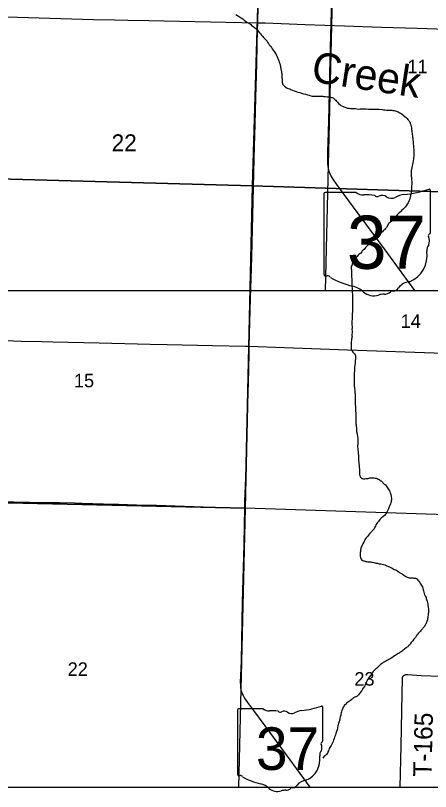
# Model space of a CAD drawing. Extents: x 0 to 68, y 0 to 52.9.
# Drawn here: x 47.275 to 48.632, y 31.129 to 33.667 of the extents above; entities that cross this region are included whole.
import ezdxf

# ---------------------------------------------------------------- set-up
doc = ezdxf.new("R2010")
doc.units = 0
for name, color, linetype in [('Default', 7, 'Continuous'), ('GM_X_Minor_River', 7, 'Continuous'), ('GM_X_Minor_River_Text', 7, 'Continuous'), ('GM_X_State_Route', 7, 'Continuous'), ('GM_X_State_Shield', 7, 'Continuous'), ('GM_X_Township_Road', 7, 'Continuous'), ('GM_X_Township_Road_Text', 7, 'Continuous')]:
    doc.layers.add(name, color=color, linetype=linetype)

msp = doc.modelspace()

# ---------------------------------------------------------------- linework, layer by layer
at = {"layer": 'Default'}
for p, q in [((41.1051, 32.7683), (50.3451, 32.7683)), ((42.2581, 31.1431), (49.6501, 31.1431))]:
    msp.add_line(p, q, dxfattribs=at)
for points in [[(47.0084, 34.1977), (48.0815, 34.1703), (48.0507, 33.11), (46.9804, 33.1394)], [(48.0815, 34.1703), (49.1337, 34.1352), (49.1093, 33.076), (48.0507, 33.11)], [(46.9804, 33.1394), (48.0507, 33.11), (48.0259, 32.0553), (46.9572, 32.0794)], [(48.0507, 33.11), (49.1093, 33.076), (49.0797, 32.0205), (48.0259, 32.0553)]]:
    msp.add_lwpolyline(points, close=True, dxfattribs=at)
for points in [[(46.955, 32.7683), (46.979, 33.9387), (48.3149, 33.9086), (48.2876, 32.7683)], [(46.938, 31.1431), (46.9572, 32.0794), (48.0259, 32.0553), (48.0041, 31.1431)]]:
    msp.add_lwpolyline(points, dxfattribs=at)
at = {"layer": 'GM_X_Minor_River'}
for points in [[(47.9962, 33.6707), (48.0006, 33.6671), (48.0078, 33.6631), (48.013, 33.6598), (48.0182, 33.6562), (48.023, 33.6526), (48.0278, 33.649), (48.0318, 33.6461), (48.0358, 33.6441), (48.0382, 33.6425), (48.0402, 33.6409), (48.0422, 33.6393), (48.0446, 33.6377), (48.0478, 33.634), (48.0527, 33.6316), (48.0555, 33.6292), (48.0583, 33.6272), (48.0611, 33.6248), (48.0639, 33.6224), (48.0663, 33.6191), (48.0695, 33.6147), (48.0731, 33.6111), (48.0763, 33.6075), (48.0795, 33.6034), (48.0831, 33.5994), (48.0875, 33.5942), (48.0911, 33.5906), (48.0943, 33.5877), (48.0963, 33.5857), (48.0979, 33.5833), (48.0995, 33.5801), (48.1023, 33.5761), (48.1051, 33.5713), (48.1087, 33.5668), (48.1119, 33.5624), (48.1147, 33.5584), (48.1179, 33.5536), (48.1211, 33.5499), (48.1231, 33.5463), (48.1255, 33.5427), (48.1279, 33.5395), (48.1291, 33.5367), (48.1307, 33.5326), (48.1363, 33.5194), (48.1375, 33.5154), (48.1391, 33.5109), (48.1407, 33.5053), (48.1419, 33.5017), (48.1423, 33.4989), (48.1431, 33.4957), (48.1434, 33.4921)], [(48.1434, 33.4921), (48.1442, 33.4897), (48.1442, 33.4873), (48.1446, 33.4844), (48.145, 33.4812), (48.1458, 33.4776), (48.1462, 33.4744), (48.1466, 33.4716), (48.1466, 33.4676), (48.1466, 33.4644), (48.147, 33.4612), (48.147, 33.4567), (48.147, 33.4531), (48.147, 33.4507), (48.1474, 33.4483), (48.1482, 33.4447), (48.1486, 33.4427), (48.1502, 33.4407), (48.1522, 33.4387), (48.1546, 33.4359), (48.159, 33.4326), (48.1634, 33.4302), (48.1678, 33.4286), (48.1718, 33.4274), (48.1758, 33.4257), (48.1806, 33.4233), (48.187, 33.4213), (48.1931, 33.4189), (48.1987, 33.4168), (48.2047, 33.4152), (48.2107, 33.4132), (48.2175, 33.4116), (48.2239, 33.4099), (48.23, 33.4083), (48.236, 33.4067), (48.2408, 33.4051), (48.2456, 33.4039), (48.2516, 33.4034), (48.2653, 33.4038), (48.2697, 33.4038), (48.2733, 33.4038), (48.2757, 33.4038), (48.2781, 33.4037), (48.2805, 33.4033), (48.2829, 33.4029), (48.2861, 33.4025), (48.2893, 33.4021), (48.2942, 33.4017), (48.2974, 33.4017), (48.301, 33.4013), (48.303, 33.4009), (48.3054, 33.4004), (48.3082, 33.3996), (48.3106, 33.3992), (48.3138, 33.398), (48.3166, 33.396), (48.3198, 33.3932), (48.3226, 33.3904), (48.3254, 33.3871), (48.3282, 33.3835), (48.3318, 33.3795), (48.3354, 33.3759), (48.3394, 33.373), (48.3443, 33.371), (48.3495, 33.3686), (48.3559, 33.3666), (48.3615, 33.3649), (48.3659, 33.3641), (48.3707, 33.3637), (48.3743, 33.3637), (48.378, 33.3637), (48.382, 33.3637), (48.3868, 33.3629), (48.3916, 33.362), (48.3968, 33.3616), (48.402, 33.362), (48.4061, 33.3624), (48.4101, 33.3624), (48.4141, 33.3624), (48.4217, 33.3619), (48.4297, 33.3615), (48.4374, 33.3611), (48.4454, 33.3611), (48.453, 33.3614), (48.4586, 33.361), (48.4634, 33.3606), (48.4747, 33.3602), (48.4787, 33.3594), (48.4835, 33.3585), (48.4891, 33.3581), (48.4931, 33.3581), (48.4972, 33.3581), (48.5012, 33.3581), (48.5056, 33.3577), (48.5096, 33.3572), (48.5136, 33.3564), (48.5172, 33.3556), (48.5208, 33.3548), (48.5236, 33.3536), (48.5268, 33.3524), (48.5317, 33.3495)], [(48.5317, 33.3495), (48.5365, 33.3467), (48.5409, 33.3439), (48.5445, 33.3407), (48.5489, 33.337), (48.5525, 33.3342), (48.5561, 33.331), (48.5589, 33.3274), (48.5617, 33.3238), (48.5641, 33.3201), (48.5657, 33.3173), (48.5665, 33.3137), (48.5677, 33.3101), (48.5689, 33.3049), (48.5701, 33.3001), (48.5709, 33.2976), (48.5709, 33.2948), (48.5713, 33.2912), (48.5716, 33.2864), (48.572, 33.282), (48.5728, 33.278), (48.5732, 33.2744), (48.5736, 33.2704), (48.5744, 33.2647), (48.5748, 33.2595), (48.5756, 33.2551), (48.576, 33.2511), (48.576, 33.2467), (48.5764, 33.2423), (48.5764, 33.239), (48.5771, 33.235), (48.5775, 33.2298), (48.5775, 33.2258), (48.5779, 33.2218), (48.5779, 33.2162), (48.5779, 33.2113), (48.5771, 33.1985), (48.5762, 33.1921), (48.575, 33.1853), (48.5738, 33.1801), (48.5726, 33.1756), (48.5714, 33.1704), (48.5702, 33.1648), (48.5693, 33.1596), (48.5689, 33.1536), (48.5689, 33.148), (48.5693, 33.1423), (48.5701, 33.1383), (48.5705, 33.1339), (48.5709, 33.1291), (48.5713, 33.1247), (48.5713, 33.1203), (48.5713, 33.1151), (48.5708, 33.1098), (48.5708, 33.1054), (48.5704, 33.1006), (48.5704, 33.0958), (48.57, 33.0918), (48.5696, 33.0886), (48.5688, 33.0842), (48.5676, 33.0793), (48.5667, 33.0757), (48.5659, 33.0733), (48.5647, 33.0697), (48.5635, 33.0649), (48.5623, 33.0621), (48.5611, 33.0601), (48.5591, 33.0549), (48.5575, 33.0509), (48.5546, 33.0477), (48.5534, 33.0449), (48.551, 33.0421), (48.5486, 33.0397), (48.5466, 33.0373), (48.5442, 33.0353), (48.5418, 33.0325), (48.5381, 33.0293), (48.5349, 33.0253), (48.5305, 33.0217), (48.5269, 33.0185), (48.5237, 33.0149), (48.5204, 33.0113), (48.5172, 33.0077), (48.5144, 33.0045), (48.512, 33.0021), (48.5039, 32.9941), (48.5015, 32.9921), (48.4987, 32.9897), (48.4967, 32.9885), (48.4951, 32.9865), (48.4902, 32.9765), (48.4886, 32.9741), (48.4866, 32.9717), (48.4842, 32.9693), (48.4818, 32.9669), (48.4798, 32.9649), (48.4778, 32.9629), (48.4754, 32.9597), (48.4713, 32.9573), (48.4685, 32.9549), (48.4653, 32.9529)], [(48.4653, 32.9529), (48.4629, 32.9509), (48.4601, 32.9481), (48.4569, 32.9449), (48.4536, 32.9425), (48.45, 32.9397), (48.4468, 32.9369), (48.444, 32.9345), (48.4412, 32.9321), (48.438, 32.9285), (48.4351, 32.9253), (48.4319, 32.9217), (48.4283, 32.9173), (48.4247, 32.9133), (48.4215, 32.9097), (48.4182, 32.9057), (48.415, 32.9025), (48.4122, 32.8997), (48.4094, 32.8973), (48.4074, 32.8945), (48.4046, 32.8901), (48.3997, 32.8869), (48.3961, 32.8833), (48.3925, 32.8793), (48.3893, 32.8761), (48.3865, 32.8733), (48.3844, 32.8705), (48.382, 32.8673), (48.3804, 32.864), (48.3788, 32.8612), (48.3772, 32.8576), (48.376, 32.8544), (48.3748, 32.8492), (48.3735, 32.846), (48.3735, 32.8428), (48.3735, 32.8392), (48.3739, 32.836), (48.3739, 32.8328), (48.3739, 32.83), (48.3739, 32.8259), (48.3743, 32.8123), (48.3747, 32.8059), (48.375, 32.8007), (48.375, 32.7946), (48.375, 32.7886), (48.3754, 32.7822), (48.3758, 32.775), (48.3762, 32.7681), (48.3766, 32.7613), (48.3769, 32.7553), (48.3773, 32.7493), (48.3777, 32.7441), (48.3777, 32.74), (48.3777, 32.7332), (48.3773, 32.7268), (48.3773, 32.7216), (48.3772, 32.7152), (48.3772, 32.7063), (48.3772, 32.6983), (48.3768, 32.6923), (48.3768, 32.6883), (48.3768, 32.6835), (48.3764, 32.6779), (48.3759, 32.6734), (48.3755, 32.6686), (48.3755, 32.6638), (48.3755, 32.6586), (48.3755, 32.6542), (48.3759, 32.6506), (48.3759, 32.6461), (48.3755, 32.6405), (48.3759, 32.6357), (48.3758, 32.6305), (48.3754, 32.6241), (48.3754, 32.6197), (48.3758, 32.6173), (48.3754, 32.614), (48.375, 32.612), (48.3746, 32.6088), (48.3742, 32.6064), (48.3742, 32.604), (48.3734, 32.5996), (48.373, 32.5964), (48.3725, 32.5936), (48.3725, 32.59), (48.3725, 32.586), (48.3725, 32.5832), (48.3725, 32.5811), (48.3725, 32.5783), (48.3733, 32.5763), (48.3757, 32.5719), (48.3789, 32.5659), (48.3837, 32.561), (48.3861, 32.5578), (48.3873, 32.5558), (48.3877, 32.5534), (48.3877, 32.5502), (48.3877, 32.547), (48.3873, 32.5426), (48.3865, 32.539), (48.3861, 32.5346)], [(48.3861, 32.5346), (48.386, 32.5297), (48.3852, 32.5233), (48.3844, 32.5157), (48.384, 32.5101), (48.3836, 32.5041), (48.3832, 32.498), (48.3827, 32.4912), (48.3827, 32.486), (48.3827, 32.4804), (48.3827, 32.474), (48.3827, 32.4655), (48.3827, 32.4607), (48.3831, 32.4563), (48.3834, 32.4479), (48.3846, 32.4394), (48.3854, 32.4334), (48.3862, 32.4302), (48.3866, 32.427), (48.3866, 32.423), (48.3862, 32.4105), (48.3862, 32.4053), (48.3861, 32.4013), (48.3865, 32.3989), (48.3865, 32.3969), (48.3865, 32.3937), (48.3869, 32.3909), (48.3873, 32.3885), (48.3877, 32.3857), (48.3877, 32.3816), (48.3877, 32.3764), (48.3877, 32.3724), (48.3881, 32.37), (48.3881, 32.3672), (48.3881, 32.3632), (48.3885, 32.3592), (48.388, 32.3564), (48.388, 32.3528), (48.388, 32.3483), (48.388, 32.3447), (48.388, 32.3395), (48.3884, 32.3355), (48.3884, 32.3319), (48.3888, 32.3283), (48.3896, 32.3243), (48.39, 32.319), (48.3903, 32.313), (48.3907, 32.3062), (48.3923, 32.2986), (48.3939, 32.2905), (48.3947, 32.2841), (48.3947, 32.2785), (48.3943, 32.2717), (48.3943, 32.2665), (48.3942, 32.2612), (48.395, 32.2456), (48.3954, 32.2404), (48.3962, 32.2347), (48.3966, 32.2291), (48.397, 32.2235), (48.3973, 32.2183), (48.3973, 32.2123), (48.3977, 32.2066), (48.3981, 32.2006), (48.3989, 32.1954), (48.3997, 32.1922), (48.3997, 32.1886), (48.4001, 32.1838), (48.4005, 32.1801), (48.4005, 32.1769), (48.4005, 32.1745), (48.4, 32.1721), (48.4, 32.1701), (48.4004, 32.1677), (48.4004, 32.1649), (48.4008, 32.1629), (48.4024, 32.1585), (48.4044, 32.1557), (48.4076, 32.1532), (48.4096, 32.1524), (48.4132, 32.152), (48.4173, 32.152), (48.4221, 32.1524), (48.4241, 32.1524), (48.4265, 32.1532), (48.4285, 32.1532), (48.4309, 32.154), (48.4341, 32.1548), (48.4377, 32.1551), (48.4422, 32.1551), (48.447, 32.1551), (48.4518, 32.1543), (48.4546, 32.1535), (48.4578, 32.1527), (48.4614, 32.1511), (48.4642, 32.1498), (48.4666, 32.1478), (48.4698, 32.1454), (48.4722, 32.1442), (48.481, 32.1345), (48.485, 32.1317)], [(48.485, 32.1317), (48.4874, 32.1285), (48.4898, 32.1257), (48.4918, 32.1225), (48.4942, 32.1192), (48.4966, 32.116), (48.4982, 32.1128), (48.4994, 32.11), (48.5006, 32.1064), (48.5018, 32.1036), (48.5026, 32.1004), (48.5034, 32.0955), (48.5042, 32.0927), (48.5046, 32.0883), (48.5046, 32.0855), (48.5046, 32.0831), (48.5042, 32.0799), (48.5034, 32.0759), (48.5026, 32.0739), (48.5014, 32.0703), (48.5005, 32.0671), (48.4993, 32.0647), (48.4985, 32.0626), (48.4977, 32.0598), (48.4965, 32.0566), (48.4949, 32.0538), (48.4933, 32.0494), (48.4913, 32.0454), (48.4888, 32.041), (48.486, 32.037), (48.4816, 32.0314), (48.4764, 32.0274), (48.4707, 32.023), (48.4667, 32.0186), (48.4643, 32.0154), (48.4619, 32.0122), (48.4591, 32.0086), (48.4566, 32.0054), (48.4542, 32.0018), (48.4522, 31.9974), (48.4502, 31.9934), (48.4478, 31.9878), (48.4441, 31.9838), (48.4421, 31.9818), (48.4405, 31.9798), (48.4329, 31.9718), (48.4301, 31.9678), (48.4268, 31.9634), (48.4224, 31.9586), (48.4192, 31.9546), (48.4172, 31.9509), (48.414, 31.9441), (48.4115, 31.9393), (48.4095, 31.9353), (48.4075, 31.9313), (48.4059, 31.9281), (48.4051, 31.9253), (48.4047, 31.9221), (48.4039, 31.9185), (48.403, 31.9141), (48.4026, 31.9105), (48.4026, 31.9073), (48.4022, 31.904), (48.4026, 31.9012), (48.4026, 31.8988), (48.403, 31.8944), (48.4042, 31.8912), (48.4054, 31.8892), (48.4078, 31.886), (48.4102, 31.8844), (48.4134, 31.8835), (48.4154, 31.8835), (48.419, 31.8823), (48.4214, 31.8815), (48.4242, 31.8811), (48.4278, 31.8807), (48.4311, 31.8807), (48.4335, 31.8803), (48.4359, 31.8799), (48.4391, 31.8794), (48.4427, 31.879), (48.4471, 31.8786), (48.4507, 31.8774), (48.4539, 31.8762), (48.4567, 31.8758), (48.4591, 31.8754), (48.4611, 31.875), (48.4644, 31.8741), (48.4676, 31.8741), (48.4704, 31.8741), (48.4836, 31.8701), (48.4892, 31.8672), (48.4948, 31.8652), (48.4988, 31.864), (48.5025, 31.8616), (48.5069, 31.8592), (48.5105, 31.8575), (48.5141, 31.8555), (48.5181, 31.8543), (48.5217, 31.8527), (48.5261, 31.8499)], [(48.5261, 31.8499), (48.5313, 31.8458), (48.5393, 31.8414), (48.5457, 31.837), (48.5514, 31.8325), (48.5562, 31.8297), (48.5598, 31.8285), (48.5622, 31.8277), (48.5646, 31.8277), (48.5678, 31.8277), (48.571, 31.8277), (48.5742, 31.8276), (48.5774, 31.8272), (48.5806, 31.8268), (48.583, 31.8264), (48.5851, 31.826), (48.5871, 31.8252), (48.5891, 31.8236), (48.5915, 31.8208), (48.5943, 31.8171), (48.5975, 31.8131), (48.6003, 31.8083), (48.6031, 31.8031), (48.6059, 31.7982), (48.6074, 31.7934), (48.6086, 31.7906), (48.609, 31.7886), (48.6098, 31.7854), (48.6106, 31.781), (48.6118, 31.7766), (48.6134, 31.7725), (48.615, 31.7697), (48.6162, 31.7669), (48.6178, 31.7633), (48.6186, 31.7601), (48.6198, 31.7569), (48.6214, 31.7516), (48.6222, 31.7476), (48.6234, 31.7424), (48.6242, 31.7384), (48.6265, 31.7247), (48.6265, 31.7203), (48.6261, 31.7175), (48.6257, 31.7139), (48.6253, 31.7107), (48.6253, 31.7083), (48.6245, 31.7059), (48.6237, 31.7015), (48.6233, 31.6975), (48.6229, 31.6938), (48.6225, 31.6902), (48.6216, 31.6878), (48.6208, 31.685), (48.6196, 31.6822), (48.6188, 31.6798), (48.6168, 31.6766), (48.6152, 31.6738), (48.6136, 31.671), (48.6124, 31.669), (48.6108, 31.667), (48.6095, 31.665), (48.6079, 31.663), (48.6059, 31.661), (48.6031, 31.6574), (48.6011, 31.6554), (48.5995, 31.6526), (48.5971, 31.651), (48.5959, 31.649), (48.5938, 31.647), (48.5918, 31.6458), (48.589, 31.6418), (48.587, 31.6394), (48.5854, 31.6366), (48.583, 31.633), (48.5802, 31.6298), (48.5781, 31.627), (48.5745, 31.6222), (48.5717, 31.619), (48.5693, 31.6162), (48.5673, 31.613), (48.5645, 31.6086), (48.562, 31.6062), (48.56, 31.6042), (48.558, 31.6022), (48.5556, 31.6006), (48.5532, 31.5986), (48.5423, 31.5902), (48.5395, 31.5882), (48.5363, 31.5858), (48.5327, 31.5838), (48.5295, 31.5818), (48.5263, 31.5802), (48.523, 31.5782), (48.5194, 31.5754), (48.515, 31.5726), (48.5106, 31.5694), (48.5058, 31.5662), (48.5001, 31.5626), (48.4961, 31.5602), (48.4929, 31.5586), (48.4897, 31.5574)], [(48.4897, 31.5574), (48.4869, 31.5558), (48.4837, 31.5542), (48.4804, 31.5522), (48.478, 31.5507), (48.4752, 31.5491), (48.4724, 31.5467), (48.4692, 31.5439), (48.466, 31.5407), (48.4631, 31.5387), (48.4603, 31.5359), (48.4579, 31.5339), (48.4559, 31.5315), (48.4531, 31.5295), (48.4511, 31.5275), (48.4483, 31.5243), (48.445, 31.5211), (48.4422, 31.5171), (48.439, 31.5127), (48.4358, 31.5087), (48.4322, 31.5034), (48.4301, 31.5002), (48.4285, 31.4978), (48.4269, 31.495), (48.4253, 31.4918), (48.4233, 31.4882), (48.4217, 31.485), (48.4205, 31.4818), (48.4192, 31.4786), (48.4176, 31.475), (48.416, 31.4718), (48.4144, 31.4682), (48.4116, 31.4658), (48.4104, 31.463), (48.4088, 31.4606), (48.4068, 31.4586), (48.3999, 31.449), (48.3967, 31.4454), (48.3935, 31.4422), (48.3911, 31.4402), (48.3882, 31.4386), (48.3854, 31.4378), (48.383, 31.4366), (48.3806, 31.435), (48.3782, 31.4334), (48.3758, 31.4314), (48.3734, 31.429), (48.371, 31.4266), (48.3677, 31.4242), (48.3641, 31.4222), (48.3609, 31.4198), (48.3573, 31.4174), (48.3545, 31.4138), (48.3509, 31.411), (48.3488, 31.4082), (48.3476, 31.4054), (48.346, 31.4026), (48.3448, 31.3994), (48.3436, 31.3966), (48.3428, 31.3934), (48.3416, 31.3894), (48.3404, 31.3858), (48.3395, 31.3818), (48.3387, 31.3781), (48.3375, 31.3733), (48.3363, 31.3689), (48.3355, 31.3653), (48.3351, 31.3625), (48.3343, 31.3601), (48.3335, 31.3577), (48.3327, 31.3549), (48.3314, 31.3513), (48.3306, 31.3473), (48.3294, 31.3433), (48.3286, 31.3376), (48.327, 31.3308), (48.3254, 31.3256), (48.3241, 31.322), (48.3233, 31.3188), (48.3221, 31.3148), (48.3205, 31.3108), (48.3189, 31.3068), (48.3169, 31.302), (48.3153, 31.2972), (48.314, 31.2927), (48.3124, 31.2883), (48.3072, 31.2791), (48.3056, 31.2763), (48.3032, 31.2727), (48.3011, 31.2691), (48.2995, 31.2651), (48.2983, 31.2619), (48.2971, 31.2587), (48.2963, 31.2559), (48.2943, 31.2527), (48.2927, 31.2503), (48.2899, 31.2483), (48.287, 31.2459), (48.285, 31.2443), (48.2826, 31.2411), (48.2802, 31.2375)]]:
    msp.add_lwpolyline(points, dxfattribs=at)
at = {"layer": 'GM_X_State_Route'}
for points in [[(48.3092, 33.7611), (48.3035, 33.5231), (48.3001, 33.3672), (48.2982, 33.2852), (48.2961, 33.2237), (48.2955, 33.199), (48.2957, 33.1825), (48.2964, 33.1742), (48.2978, 33.166), (48.2999, 33.158), (48.3029, 33.1503), (48.3066, 33.1428), (48.3129, 33.1321), (48.3245, 33.1151), (48.3488, 33.0821), (48.3951, 33.0193), (48.4828, 32.9004), (48.5384, 32.8242), (48.5799, 32.7683)], [(48.069, 33.716), (48.0669, 33.6569), (48.0666, 33.6437), (48.0659, 33.6175), (48.0648, 33.5716), (48.0632, 33.5092), (48.06, 33.3977), (48.0576, 33.3123), (48.0547, 33.2007), (48.0536, 33.1515), (48.05, 33.0137), (48.0464, 32.8791), (48.0453, 32.8397), (48.043, 32.7413), (48.0387, 32.5858), (48.038, 32.5608), (48.0355, 32.4657), (48.0319, 32.3442), (48.0307, 32.2884), (48.029, 32.2392), (48.0268, 32.1539), (48.0245, 32.0784), (48.0241, 32.0567), (48.0214, 31.9373), (48.0168, 31.7469), (48.0141, 31.6222), (48.0126, 31.5566), (48.0109, 31.5074), (48.0104, 31.4877), (48.0106, 31.4744), (48.0111, 31.4678), (48.0122, 31.4613), (48.0139, 31.4548), (48.0164, 31.4487), (48.0193, 31.4427), (48.0243, 31.4342), (48.0336, 31.4205), (48.0531, 31.3941), (48.0901, 31.3439), (48.1602, 31.2487), (48.2047, 31.1878), (48.238, 31.1431)]]:
    msp.add_lwpolyline(points, dxfattribs=at)
at = {"layer": 'GM_X_State_Shield'}
for p, q in [((48.2841, 33.0843), (48.2841, 32.8201)), ((48.3895, 33.0888), (48.2876, 33.0888)), ((48.6322, 32.9572), (48.6322, 33.0954)), ((48.6321, 32.9572), (48.6322, 32.9572)), ((48.2798, 31.2942), (48.2798, 31.4047)), ((48.0013, 31.3959), (48.0013, 31.1845)), ((48.0856, 31.3995), (48.0041, 31.3995)), ((48.2797, 31.2942), (48.2798, 31.2942))]:
    msp.add_line(p, q, dxfattribs=at)
for centre, radius, start, end in [((48.2881, 33.0849), 0.00403, 98.1301, 188.1301), ((48.4138, 33.1195), 0.0391, 231.6195, 271.1119), ((48.4267, 32.9405), 0.1404, 80.4867, 94.9883), ((48.4586, 33.0862), 0.0113, 219.7921, 297.1024), ((48.4752, 33.0557), 0.0235, 54.4667, 119.1411), ((48.5553, 33.0082), 0.0743, 97.3462, 120.7689), ((48.5082, 33.449), 0.3691, 275.8445, 288.9065), ((48.6283, 33.096), 0.00387, 351.8621, 97.738), ((48.5054, 33.0976), 0.0282, 233.8562, 294.8282), ((48.6313, 32.9471), 0.006, 107.944, 210.337), ((48.6281, 32.9567), 0.00415, 289.6038, 7.7341), ((48.5931, 32.9296), 0.036, 340.033, 23.6496), ((48.6461, 32.8994), 0.0262, 136.8065, 186.9296), ((48.5289, 32.8818), 0.0923, 292.3089, 8.9858), ((48.2882, 32.8196), 0.00407, 171.9584, 258.3066), ((48.2888, 32.8466), 0.031, 267.339, 280.6039), ((48.2951, 32.8049), 0.0112, 29.7484, 93.2717), ((48.4365, 33.0422), 0.2665, 240.4129, 257.1985), ((48.357, 32.7015), 0.0834, 47.1842, 75.836), ((48.5037, 32.7945), 0.0298, 282.8732, 323.2771), ((48.5678, 32.746), 0.0506, 94.4031, 142.5768), ((48.4472, 32.8036), 0.0529, 230.7004, 286.2918), ((48.4778, 32.7123), 0.0435, 85.6951, 111.2099), ((48.4816, 32.7838), 0.0282, 268.777, 315.5493), ((48.5071, 32.7582), 0.00794, 65.7517, 132.6484), ((48.1806, 31.6876), 0.2953, 275.8445, 288.9065), ((48.2767, 31.4052), 0.0031, 351.8621, 97.738), ((48.0045, 31.3963), 0.00323, 98.1301, 188.1301), ((48.105, 31.424), 0.0313, 231.6195, 271.1119), ((48.1154, 31.2809), 0.1123, 80.4867, 94.9883), ((48.1409, 31.3974), 0.00903, 219.7921, 297.1024), ((48.1542, 31.373), 0.0188, 54.4667, 119.1411), ((48.1784, 31.4065), 0.0226, 233.8562, 294.8282), ((48.2182, 31.335), 0.0594, 97.3462, 120.7689), ((48.279, 31.2861), 0.0048, 107.944, 210.337), ((48.2485, 31.2721), 0.0288, 340.033, 23.6496), ((48.2765, 31.2938), 0.00332, 289.6038, 7.7341), ((48.2909, 31.2479), 0.021, 136.8065, 186.9296), ((48.1971, 31.2339), 0.0739, 292.3089, 8.9858), ((48.0046, 31.1841), 0.00325, 171.9584, 258.3066), ((48.005, 31.2057), 0.0248, 267.339, 280.6039), ((48.0101, 31.1724), 0.00895, 29.7484, 93.2717), ((48.1232, 31.3622), 0.2132, 240.4129, 257.1985), ((48.0596, 31.0896), 0.0667, 47.1842, 75.836), ((48.177, 31.1641), 0.0239, 282.8732, 323.2771), ((48.2283, 31.1252), 0.0404, 94.4031, 142.5768), ((48.1318, 31.1713), 0.0423, 230.7004, 286.2918), ((48.1562, 31.0982), 0.0348, 85.6951, 111.2099), ((48.1593, 31.1555), 0.0226, 268.777, 315.5493), ((48.1797, 31.135), 0.00635, 65.7517, 132.6484)]:
    msp.add_arc(centre, radius, start, end, dxfattribs=at)
at = {"layer": 'GM_X_Township_Road'}
for points in [[(46.9948, 33.6707), (47.1399, 33.6664), (47.2809, 33.6618), (47.5303, 33.6544), (47.5992, 33.6529), (47.6419, 33.6518), (47.7108, 33.6508), (47.9635, 33.6458), (48.0666, 33.6437)], [(48.0666, 33.6437), (48.0915, 33.6432), (48.2228, 33.6385), (48.3507, 33.6341), (48.4721, 33.6298), (48.5902, 33.626), (48.7476, 33.6208), (49.033, 33.6112), (49.1085, 33.6085), (49.1183, 33.6081), (49.1244, 33.6078)], [(46.9702, 32.6103), (46.978, 32.6102), (47.037, 32.6091), (47.1244, 32.607), (47.2172, 32.6049), (47.2932, 32.6026), (47.3621, 32.6012), (47.3975, 32.6001), (47.5484, 32.5966), (47.7156, 32.5928), (47.7714, 32.5914), (47.919, 32.5883), (48.0272, 32.5862), (48.0387, 32.5858)], [(48.0387, 32.5858), (48.1551, 32.5819), (48.3614, 32.5736), (48.6762, 32.5628), (48.7712, 32.5594), (48.8237, 32.5578), (49.0965, 32.5481)], [(46.958, 32.0816), (47.0023, 32.0811), (47.0975, 32.0792), (47.2681, 32.0765), (47.3206, 32.0756), (47.3665, 32.0749), (47.4191, 32.0739), (47.4679, 32.0731), (47.4939, 32.0723), (47.5266, 32.0715), (47.5626, 32.0704), (47.6118, 32.069), (47.7003, 32.0661), (47.7364, 32.0652), (47.9201, 32.0596), (47.9955, 32.057), (48.0184, 32.0568), (48.0241, 32.0567)], [(48.5332, 31.1431), (48.5365, 31.2785), (48.5403, 31.4492), (48.5406, 31.4986), (48.5408, 31.5019), (48.5417, 31.505), (48.5435, 31.5076), (48.546, 31.5096), (48.5491, 31.5108), (48.5523, 31.5114), (48.5589, 31.5112), (48.6015, 31.5087), (48.7557, 31.5025), (48.782, 31.5016), (48.7951, 31.5024), (48.8146, 31.5048), (48.8277, 31.5053), (48.8639, 31.5041), (48.9951, 31.4977), (49.0593, 31.4943)]]:
    msp.add_lwpolyline(points, dxfattribs=at)

# ---------------------------------------------------------------- texts
at = {"layer": 'Default'}
for s, height, p in [('11', 0.0442, (48.557, 33.4785)), ('22', 0.05525, (47.5894, 33.2235)), ('14', 0.0442, (48.535, 32.6455)), ('15', 0.0442, (47.4662, 32.4512)), ('22', 0.0442, (47.4455, 31.5072)), ('23', 0.0442, (48.3836, 31.4752))]:
    msp.add_text(s, height=height, rotation=0, dxfattribs=at).set_placement(p)
at = {"layer": 'GM_X_Minor_River_Text'}
msp.add_text('Creek', height=0.10004, rotation=351.3025, dxfattribs=at).set_placement((48.2393, 33.4517))
at = {"layer": 'GM_X_State_Shield'}
for height, p in [(0.17402, (48.3592, 32.8388)), (0.13922, (48.0614, 31.1995))]:
    msp.add_text('37', height=height, dxfattribs=at).set_placement(p)
at = {"layer": 'GM_X_Township_Road_Text'}
msp.add_text('T-165', height=0.06, rotation=88.5957, dxfattribs=at).set_placement((48.6356, 31.1767))

doc.saveas('drawing.dxf')
